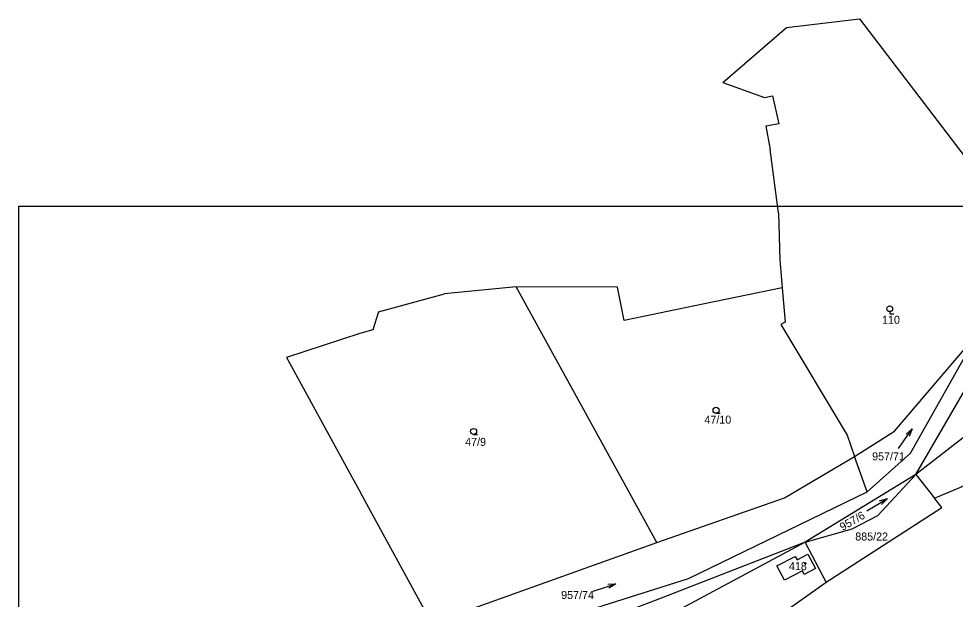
# Model space of a CAD drawing. Extents: x -752184 to -751416, y -1028299 to -1027836.
# Drawn here: x -751880.8 to -751646.8, y -1027995.9 to -1027850.8 of the extents above; entities that cross this region are included whole.
import ezdxf

# ---------------------------------------------------------------- set-up
doc = ezdxf.new("R2010")
doc.units = 0
for name, color, linetype in [('Vrstva 4', 7, 'Continuous'), ('Vrstva 55', 7, 'Continuous'), ('Vrstva 57', 7, 'Continuous'), ('Vrstva 58', 7, 'Continuous'), ('Vrstva 59', 7, 'Continuous')]:
    doc.layers.add(name, color=color, linetype=linetype)

msp = doc.modelspace()

# ---------------------------------------------------------------- linework, layer by layer
at = {"layer": 'Vrstva 4'}
msp.add_lwpolyline([(-751880.79, -1027897.6), (-751466.79, -1027897.6), (-751466.79, -1028188.6), (-751880.79, -1028188.6)], close=True, dxfattribs=at)
at = {"layer": 'Vrstva 55'}
for p, q in [((-751670.74, -1027850.8), (-751644.31, -1027885.35)), ((-751704.87, -1027866.74), (-751694.47, -1027870.45)), ((-751690.99, -1027899.26), (-751693.06, -1027883.49)), ((-751656.71, -1027964.65), (-751615.69, -1027894.18)), ((-751690.99, -1027899.26), (-751690.67, -1027911.02)), ((-751690.67, -1027911.02), (-751690.06, -1027918.02)), ((-751756.49, -1027917.81), (-751774.43, -1027919.56)), ((-751721.34, -1027981.66), (-751756.49, -1027917.81)), ((-751731.23, -1027917.9), (-751756.49, -1027917.81)), ((-751729.53, -1027926.17), (-751731.23, -1027917.9)), ((-751690.06, -1027918.02), (-751709.85, -1027922.12)), ((-751790.91, -1027924.02), (-751774.43, -1027919.56)), ((-751709.85, -1027922.12), (-751729.53, -1027926.17)), ((-751790.91, -1027924.02), (-751792.3, -1027928.54)), ((-751795.59, -1027929.43), (-751813.91, -1027935.42)), ((-751792.3, -1027928.54), (-751795.59, -1027929.43)), ((-751813.91, -1027935.42), (-751813.18, -1027936.76)), ((-751813.18, -1027936.76), (-751798.39, -1027963.79)), ((-751668.79, -1027968.97), (-751672, -1027960.17)), ((-751798.39, -1027963.79), (-751795.36, -1027969.33)), ((-751656.71, -1027964.65), (-751684.34, -1027981.6)), ((-751656.71, -1027964.65), (-751651.99, -1027970.58)), ((-751777.61, -1028001.77), (-751795.36, -1027969.33)), ((-751777.61, -1028001.77), (-751721.34, -1027981.66)), ((-751684.34, -1027981.6), (-751719.87, -1028000.62)), ((-751679.08, -1027991.59), (-751684.34, -1027981.6))]:
    msp.add_line(p, q, dxfattribs=at)
for points in [[(-751704.87, -1027866.74), (-751689.01, -1027853.02), (-751670.74, -1027850.8)], [(-751694.47, -1027870.45), (-751692.52, -1027870.09), (-751690.89, -1027877.03), (-751694.15, -1027877.64), (-751693.06, -1027883.49)], [(-751690.06, -1027918.02), (-751689.33, -1027926.62), (-751690.4, -1027927.23), (-751673.79, -1027954.88), (-751672, -1027960.17)], [(-751672, -1027960.17), (-751661.99, -1027953.87), (-751641.14, -1027929.37)], [(-751668.79, -1027968.97), (-751658.03, -1027959.34), (-751641.14, -1027929.37)], [(-751626.99, -1027930.26), (-751643.3, -1027954.3), (-751656.71, -1027964.65)], [(-751651.99, -1027970.58), (-751636.62, -1027964.12), (-751616.15, -1027952.42)], [(-751721.34, -1027981.66), (-751689.52, -1027970.51), (-751672, -1027960.17)], [(-751684.34, -1027981.6), (-751672.55, -1027978.29), (-751666.13, -1027974.89), (-751656.71, -1027964.65)], [(-751865.7, -1028042.71), (-751749.56, -1028002.08), (-751713.49, -1027990.7), (-751668.79, -1027968.97)], [(-751679.08, -1027991.59), (-751650.14, -1027972.91), (-751651.99, -1027970.58)], [(-751684.34, -1027981.6), (-751721.79, -1027996.16), (-751725.3, -1027997.51), (-751759.96, -1028010.88)], [(-751686.34, -1027986.01), (-751683.66, -1027984.6), (-751681.77, -1027988.19), (-751684.55, -1027989.66), (-751685.01, -1027988.78), (-751689.45, -1027991.12), (-751691.36, -1027987.53), (-751686.8, -1027985.13), (-751686.34, -1027986.01)], [(-751719.87, -1028000.62), (-751712.01, -1028018.94), (-751709.09, -1028017.63), (-751700.97, -1028007.7), (-751696.27, -1028003.7), (-751679.08, -1027991.59)]]:
    msp.add_lwpolyline(points, dxfattribs=at)
at = {"layer": 'Vrstva 58'}
for p, q in [((-751663.2, -1027923.99), (-751663.2, -1027924.54)), ((-751663.2, -1027924.54), (-751662.2, -1027924.54)), ((-751706.59, -1027949.38), (-751705.59, -1027949.38)), ((-751661.01, -1027958.18), (-751657.56, -1027953.27)), ((-751767.16, -1027954.67), (-751766.16, -1027954.67)), ((-751668.92, -1027973.77), (-751663.77, -1027970.7)), ((-751737.32, -1027993.8), (-751731.6, -1027991.98))]:
    msp.add_line(p, q, dxfattribs=at)
for points in [[(-751659.12, -1027954.62), (-751657.56, -1027953.27), (-751658.3, -1027955.2)], [(-751665.74, -1027971.29), (-751663.77, -1027970.7), (-751665.23, -1027972.15)], [(-751733.66, -1027992.11), (-751731.6, -1027991.98), (-751733.36, -1027993.06)]]:
    msp.add_lwpolyline(points, dxfattribs=at)
for centre, radius in [((-751663.2, -1027923.26), 0.725), ((-751706.59, -1027948.63), 0.75), ((-751767.16, -1027953.92), 0.75)]:
    msp.add_circle(centre, radius, dxfattribs=at)
at = {"layer": 'Vrstva 59'}
msp.add_circle((-751684.3, -1027986.91), 0.175, dxfattribs=at)

# ---------------------------------------------------------------- texts
at = {"layer": 'Vrstva 57'}
for s, p in [('110', (-751665.11, -1027927.02)), ('47/10', (-751709.48, -1027951.97)), ('47/9', (-751769.26, -1027957.52)), ('957/71', (-751667.59, -1027961.14)), ('885/22', (-751671.8, -1027981.17)), ('418', (-751688.38, -1027988.58)), ('957/74', (-751745.28, -1027995.78))]:
    msp.add_text(s, height=2, dxfattribs=at).set_placement(p)
msp.add_text('957/6', height=2, rotation=30, dxfattribs=at).set_placement((-751674.97, -1027978.83))

doc.saveas('drawing.dxf')
